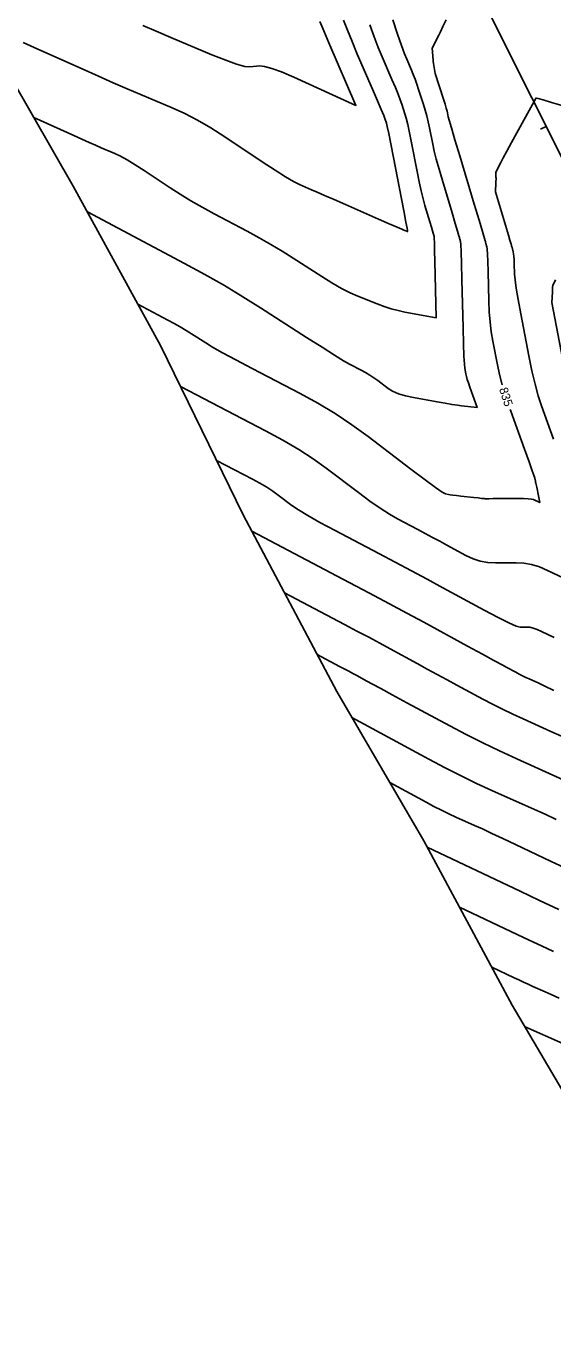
# Model space of a CAD drawing. Extents: x 1715724 to 1716561, y 394063 to 395906.
# Drawn here: x 1716259.8 to 1716345.4, y 394300.9 to 394512.3 of the extents above; entities that cross this region are included whole.
import ezdxf

# ---------------------------------------------------------------- set-up
doc = ezdxf.new("R2010")
doc.units = 0
for name, color, linetype in [('DT_X_Contour_Major', 7, 'Continuous'), ('DT_X_Contour_Minor', 7, 'Continuous'), ('DT_X_TIN_Hull', 7, 'Continuous'), ('GE_P_CL_10', 7, 'Continuous')]:
    doc.layers.add(name, color=color, linetype=linetype)

msp = doc.modelspace()

# ---------------------------------------------------------------- linework, layer by layer
at = {"layer": 'DT_X_Contour_Major'}
for points in [[(1716328.01, 394513.3), (1716327.5, 394512.22), (1716327.1, 394511.39), (1716326.82, 394510.82), (1716325.77, 394508.73), (1716325.85, 394507.49), (1716325.87, 394507.21), (1716325.9, 394506.91), (1716325.94, 394506.59), (1716325.98, 394506.25), (1716326.22, 394504.61), (1716327.59, 394500.44), (1716327.85, 394499.63), (1716328.05, 394498.99), (1716328.19, 394498.52), (1716328.26, 394498.21), (1716328.38, 394497.6), (1716328.53, 394497.03), (1716328.89, 394495.79), (1716329.46, 394493.86), (1716330.24, 394491.25), (1716332.6, 394483.38), (1716333.37, 394480.79), (1716333.93, 394478.95), (1716334.26, 394477.84), (1716334.37, 394477.47), (1716334.37, 394477.45), (1716334.38, 394477.43), (1716334.4, 394477.35), (1716334.43, 394477.22), (1716334.48, 394477.04), (1716334.63, 394476.5), (1716334.68, 394476.09), (1716334.73, 394475.29), (1716334.78, 394474.09), (1716334.83, 394472.49), (1716334.95, 394467.68), (1716335.03, 394465.92), (1716335.16, 394464.25), (1716335.35, 394462.67), (1716335.6, 394461.18), (1716336.34, 394457.31), (1716336.69, 394455.76), (1716337.14, 394454.1)], [(1716338.44, 394450.1), (1716338.55, 394449.79), (1716340.75, 394443.62), (1716341.48, 394441.6), (1716342, 394440.14), (1716342.31, 394439.25), (1716342.42, 394438.94), (1716342.44, 394438.86), (1716342.45, 394438.82), (1716342.45, 394438.79), (1716342.46, 394438.75), (1716342.49, 394438.59), (1716342.51, 394438.53), (1716342.53, 394438.43), (1716342.55, 394438.3), (1716342.59, 394438.14), (1716342.73, 394437.45), (1716342.78, 394437.21), (1716342.84, 394436.92), (1716342.91, 394436.59), (1716343.23, 394434.96), (1716342.21, 394435.45), (1716341.88, 394435.54), (1716341.33, 394435.6), (1716340.56, 394435.63), (1716339.57, 394435.64), (1716336.64, 394435.61), (1716335.68, 394435.61), (1716334.97, 394435.6), (1716334.53, 394435.6), (1716334.35, 394435.6), (1716334.22, 394435.61), (1716334.07, 394435.63), (1716333.74, 394435.66), (1716333.23, 394435.72), (1716332.53, 394435.8), (1716330.4, 394436.03), (1716329.68, 394436.11), (1716329.11, 394436.18), (1716328.69, 394436.24), (1716328.42, 394436.28), (1716327.9, 394436.37), (1716327.4, 394436.65), (1716326.3, 394437.41), (1716324.6, 394438.66), (1716322.3, 394440.4), (1716315.34, 394445.68), (1716312.7, 394447.6), (1716309.98, 394449.41), (1716307.18, 394451.1), (1716304.3, 394452.68), (1716296.53, 394456.73), (1716293.87, 394458.12), (1716291.73, 394459.28), (1716290.1, 394460.2), (1716288.98, 394460.88), (1716286.67, 394462.36), (1716285.79, 394462.91), (1716284.86, 394463.47), (1716283.88, 394464.03), (1716282.86, 394464.58), (1716277.98, 394467.17)], [(1716347.05, 394389.99), (1716339.51, 394393.37), (1716336.71, 394394.66), (1716333.96, 394395.99), (1716331.26, 394397.34), (1716328.62, 394398.74), (1716321.64, 394402.5), (1716319.27, 394403.78), (1716317.4, 394404.79), (1716316.04, 394405.53), (1716315.17, 394406), (1716313.52, 394406.89), (1716312.89, 394407.24), (1716312.21, 394407.6), (1716311.49, 394407.99), (1716310.72, 394408.39), (1716307.06, 394410.32)], [(1716346.4, 394354.56), (1716345.06, 394355.15), (1716344.12, 394355.57), (1716342.11, 394356.46), (1716341.36, 394356.8), (1716340.6, 394357.15), (1716339.83, 394357.5), (1716339.06, 394357.86), (1716335.44, 394359.58)]]:
    msp.add_lwpolyline(points, dxfattribs=at)
at = {"layer": 'DT_X_Contour_Minor'}
for points in [[(1716311.36, 394513.28), (1716311.99, 394511.63), (1716312.74, 394509.78), (1716313.6, 394507.75), (1716316.06, 394502.08), (1716316.88, 394500.19), (1716317.49, 394498.76), (1716317.89, 394497.79), (1716318.09, 394497.28), (1716318.32, 394496.56), (1716318.46, 394496.01), (1716318.7, 394494.89), (1716319.04, 394493.21), (1716319.48, 394490.97), (1716320.77, 394484.25), (1716321.2, 394482.04), (1716321.5, 394480.46), (1716321.69, 394479.5), (1716321.75, 394479.18), (1716321.76, 394479.14), (1716321.77, 394479.13), (1716321.77, 394479.12), (1716321.77, 394479.11), (1716321.77, 394479.1), (1716321.77, 394479.06), (1716321.77, 394479.05), (1716321.77, 394479.04), (1716321.77, 394479.04), (1716321.77, 394479.03), (1716321.77, 394479.03), (1716321.77, 394479.03), (1716321.77, 394479.03), (1716321.77, 394479.02), (1716321.77, 394479.01), (1716321.78, 394478.95), (1716321.75, 394478.96), (1716321.73, 394478.96), (1716321.71, 394478.97), (1716321.68, 394478.98), (1716321.63, 394479), (1716321.5, 394479.05), (1716321.45, 394479.07), (1716321.4, 394479.09), (1716321.35, 394479.11), (1716321.29, 394479.13), (1716321.14, 394479.19), (1716320.84, 394479.32), (1716320.06, 394479.66), (1716318.78, 394480.22), (1716317.02, 394480.99), (1716311.67, 394483.34), (1716309.82, 394484.15), (1716308.29, 394484.82), (1716307.08, 394485.35), (1716306.18, 394485.74), (1716304.19, 394486.6), (1716303.26, 394487.07), (1716301.94, 394487.84), (1716300.24, 394488.91), (1716298.15, 394490.28), (1716292.07, 394494.34), (1716289.83, 394495.77), (1716287.67, 394497.03), (1716285.58, 394498.12), (1716283.56, 394499.03), (1716278.29, 394501.25), (1716276.22, 394502.13), (1716273.97, 394503.1), (1716271.55, 394504.17), (1716268.94, 394505.34), (1716261.75, 394508.57), (1716259.37, 394509.64)], [(1716315.63, 394512.49), (1716316.33, 394510.55), (1716316.99, 394508.83), (1716317.62, 394507.33), (1716319.23, 394503.62), (1716319.78, 394502.32), (1716320.23, 394501.23), (1716320.58, 394500.34), (1716320.82, 394499.65), (1716321.34, 394498.08), (1716321.55, 394497.34), (1716321.8, 394496.31), (1716322.08, 394494.99), (1716322.4, 394493.38), (1716323.31, 394488.7), (1716323.64, 394487.04), (1716323.96, 394485.57), (1716324.28, 394484.29), (1716324.58, 394483.2), (1716325.37, 394480.56), (1716325.64, 394479.69), (1716325.82, 394479.06), (1716325.93, 394478.68), (1716325.97, 394478.55), (1716325.97, 394478.53), (1716325.97, 394478.51), (1716325.98, 394478.48), (1716325.99, 394478.43), (1716326.01, 394478.37), (1716326.06, 394478.19), (1716326.08, 394477.88), (1716326.11, 394477.11), (1716326.15, 394475.85), (1716326.2, 394474.13), (1716326.43, 394464.97), (1716321.34, 394465.89), (1716320.24, 394466.12), (1716319.12, 394466.42), (1716317.98, 394466.79), (1716316.81, 394467.22), (1716313.66, 394468.47), (1716312.42, 394469.02), (1716311.02, 394469.73), (1716309.49, 394470.61), (1716307.82, 394471.65), (1716303.17, 394474.64), (1716301.4, 394475.76), (1716299.56, 394476.86), (1716297.65, 394477.94), (1716295.69, 394479.01), (1716290.35, 394481.84), (1716288.4, 394482.9), (1716286.56, 394483.96), (1716284.83, 394485.01), (1716283.21, 394486.06), (1716279.01, 394488.85), (1716277.54, 394489.81), (1716276.24, 394490.6), (1716275.14, 394491.21), (1716274.22, 394491.64), (1716272.01, 394492.57), (1716271.11, 394492.95), (1716270.07, 394493.41), (1716268.89, 394493.93), (1716267.57, 394494.52), (1716261.08, 394497.44)], [(1716319.36, 394513.3), (1716320.14, 394511), (1716320.78, 394509.17), (1716321.27, 394507.81), (1716321.63, 394506.91), (1716322.39, 394505.15), (1716322.68, 394504.46), (1716322.97, 394503.71), (1716323.27, 394502.89), (1716323.56, 394502.02), (1716324.35, 394499.59), (1716324.64, 394498.67), (1716324.9, 394497.74), (1716325.13, 394496.77), (1716325.33, 394495.79), (1716325.84, 394493.15), (1716326.08, 394492.03), (1716326.43, 394490.68), (1716326.87, 394489.07), (1716327.41, 394487.22), (1716328.99, 394481.97), (1716329.5, 394480.24), (1716329.87, 394479), (1716330.1, 394478.26), (1716330.17, 394478.01), (1716330.17, 394477.99), (1716330.18, 394477.97), (1716330.19, 394477.91), (1716330.21, 394477.82), (1716330.25, 394477.7), (1716330.34, 394477.34), (1716330.39, 394476.86), (1716330.44, 394475.67), (1716330.5, 394473.78), (1716330.57, 394471.18), (1716330.77, 394463.34), (1716330.84, 394460.72), (1716330.91, 394458.75), (1716330.98, 394457.43), (1716331.05, 394456.76), (1716331.23, 394455.84), (1716331.32, 394455.44), (1716331.45, 394454.96), (1716331.64, 394454.39), (1716331.87, 394453.72), (1716333.06, 394450.4), (1716330.52, 394450.68), (1716329.86, 394450.76), (1716328.98, 394450.89), (1716327.88, 394451.08), (1716326.56, 394451.31), (1716322.74, 394452), (1716321.41, 394452.29), (1716320.28, 394452.63), (1716319.34, 394453.03), (1716318.61, 394453.48), (1716316.92, 394454.77), (1716316.27, 394455.23), (1716315.61, 394455.67), (1716314.93, 394456.09), (1716314.23, 394456.47), (1716312.34, 394457.45), (1716311.37, 394458), (1716309.88, 394458.91), (1716307.87, 394460.17), (1716305.34, 394461.79), (1716297.9, 394466.58), (1716295.03, 394468.38), (1716292.02, 394470.18), (1716288.86, 394471.97), (1716285.55, 394473.77), (1716269.77, 394482.14)], [(1716278.79, 394512.38), (1716280.93, 394511.46), (1716283.31, 394510.46), (1716289.97, 394507.66), (1716292.23, 394506.75), (1716294.01, 394506.12), (1716295.32, 394505.76), (1716296.16, 394505.68), (1716297.75, 394505.84), (1716298.55, 394505.77), (1716299.73, 394505.44), (1716301.31, 394504.86), (1716303.28, 394504.01), (1716313.38, 394499.44), (1716308.99, 394509.56), (1716308.15, 394511.51), (1716307.5, 394513.04)], [(1716347.05, 394499.35), (1716345.15, 394499.91), (1716343.8, 394500.31), (1716342.99, 394500.55), (1716342.71, 394500.63), (1716342.66, 394500.65), (1716338.66, 394493.39), (1716337.89, 394492), (1716337.3, 394490.93), (1716336.9, 394490.18), (1716336.68, 394489.76), (1716336.08, 394488.53), (1716336.12, 394487.78), (1716336.13, 394487.6), (1716336.13, 394487.39), (1716336.12, 394487.13), (1716336.1, 394486.84), (1716336.03, 394485.4), (1716337.81, 394479.47), (1716338.14, 394478.35), (1716338.38, 394477.56), (1716338.52, 394477.08), (1716338.57, 394476.92), (1716338.57, 394476.92), (1716338.58, 394476.88), (1716338.61, 394476.78), (1716338.65, 394476.61), (1716338.72, 394476.37), (1716338.91, 394475.65), (1716338.98, 394475.33), (1716339.03, 394474.91), (1716339.07, 394474.4), (1716339.09, 394473.79), (1716339.14, 394472.02), (1716339.22, 394471.12), (1716339.41, 394469.75), (1716339.72, 394467.91), (1716340.15, 394465.59), (1716341.46, 394458.79), (1716341.95, 394456.37), (1716342.46, 394454.21), (1716342.98, 394452.3), (1716343.52, 394450.66), (1716344.96, 394446.62), (1716345.44, 394445.28)], [(1716345.8, 394471.1), (1716345.33, 394470.2), (1716345.32, 394469.94), (1716345.32, 394469.85), (1716345.31, 394469.68), (1716345.3, 394469.43), (1716345.28, 394469.11), (1716345.2, 394467.44), (1716347.14, 394457.3)], [(1716350.61, 394421.08), (1716344.5, 394423.97), (1716343.19, 394424.52), (1716341.91, 394424.9), (1716340.63, 394425.13), (1716339.37, 394425.2), (1716336.03, 394425.17), (1716334.79, 394425.24), (1716333.57, 394425.47), (1716332.39, 394425.86), (1716331.22, 394426.4), (1716328.15, 394428.07), (1716326.99, 394428.7), (1716325.82, 394429.33), (1716324.62, 394429.97), (1716323.41, 394430.61), (1716320.14, 394432.33), (1716318.83, 394433.08), (1716317.33, 394434.04), (1716315.64, 394435.21), (1716313.77, 394436.6), (1716308.54, 394440.57), (1716306.45, 394442.07), (1716304.12, 394443.58), (1716301.53, 394445.1), (1716298.7, 394446.64), (1716284.89, 394453.83)], [(1716345.58, 394413.07), (1716343.53, 394414.05), (1716342.8, 394414.37), (1716342.17, 394414.59), (1716341.62, 394414.73), (1716341.16, 394414.77), (1716340.06, 394414.76), (1716339.39, 394414.93), (1716338.18, 394415.44), (1716336.46, 394416.3), (1716334.2, 394417.49), (1716327.49, 394421.15), (1716324.96, 394422.52), (1716322.38, 394423.9), (1716319.77, 394425.3), (1716317.11, 394426.7), (1716309.98, 394430.45), (1716307.53, 394431.76), (1716305.55, 394432.88), (1716304.03, 394433.8), (1716302.97, 394434.52), (1716300.75, 394436.2), (1716299.87, 394436.84), (1716298.89, 394437.48), (1716297.79, 394438.12), (1716296.59, 394438.77), (1716290.76, 394441.81)], [(1716345.49, 394404.45), (1716343.95, 394405.23), (1716343.06, 394405.66), (1716341.53, 394406.35), (1716340.96, 394406.61), (1716340.4, 394406.88), (1716339.86, 394407.15), (1716339.32, 394407.44), (1716337.9, 394408.2), (1716337.11, 394408.63), (1716335.78, 394409.35), (1716333.91, 394410.37), (1716331.51, 394411.67), (1716324.4, 394415.54), (1716321.65, 394417.04), (1716318.71, 394418.61), (1716315.59, 394420.27), (1716312.29, 394422.01), (1716296.47, 394430.33)], [(1716346.77, 394397.04), (1716345.05, 394397.82), (1716340.52, 394399.86), (1716338.83, 394400.64), (1716337.18, 394401.43), (1716335.56, 394402.25), (1716333.97, 394403.09), (1716329.77, 394405.35), (1716328.19, 394406.21), (1716326.59, 394407.07), (1716324.97, 394407.95), (1716323.34, 394408.84), (1716318.96, 394411.22), (1716317.27, 394412.14), (1716315.46, 394413.11), (1716313.54, 394414.13), (1716311.51, 394415.2), (1716301.77, 394420.32)], [(1716345.91, 394383.55), (1716344.08, 394384.38), (1716341.86, 394385.38), (1716335.42, 394388.27), (1716332.97, 394389.4), (1716330.45, 394390.62), (1716327.87, 394391.93), (1716325.22, 394393.33), (1716312.7, 394400.09)], [(1716347.2, 394375.73), (1716345.07, 394376.74), (1716339.28, 394379.49), (1716337.23, 394380.45), (1716335.45, 394381.29), (1716333.92, 394382), (1716332.65, 394382.57), (1716329.61, 394383.94), (1716328.45, 394384.48), (1716327.26, 394385.05), (1716326.04, 394385.67), (1716324.79, 394386.33), (1716318.87, 394389.52)], [(1716346.3, 394368.95), (1716343.21, 394370.39), (1716340.02, 394371.89), (1716324.95, 394379.05)], [(1716345.48, 394362.13), (1716343.51, 394363.02), (1716341.53, 394363.94), (1716339.54, 394364.88), (1716330.19, 394369.32)], [(1716353.09, 394344.48), (1716340.83, 394349.89)]]:
    msp.add_lwpolyline(points, dxfattribs=at)
at = {"layer": 'DT_X_TIN_Hull'}
msp.add_lwpolyline([(1716124.57, 394620.66), (1716148.93, 394620.11), (1716178.47, 394618.57), (1716198.37, 394601.55), (1716214.15, 394581.11), (1716226.91, 394558.69), (1716239.76, 394534.12), (1716254, 394509.73), (1716267.48, 394486.32), (1716281.65, 394460.47), (1716295.06, 394433.01), (1716310.25, 394404.29), (1716324.4, 394380.06), (1716338.75, 394353.43), (1716352.69, 394329.7), (1716364.18, 394305.34), (1716366.88, 394280.88)], dxfattribs=at)
at = {"layer": 'GE_P_CL_10'}
for p, q in [((1716447.81, 394289.08), (1716249.46, 394685.42)), ((1716344.25, 394496.01), (1716343.36, 394495.56))]:
    msp.add_line(p, q, dxfattribs=at)

# ---------------------------------------------------------------- texts
at = {"layer": 'DT_X_Contour_Major'}
msp.add_text('835', height=1.4, rotation=288.0616, dxfattribs=at).set_placement((1716336.6, 394453.4))

doc.saveas('drawing.dxf')
